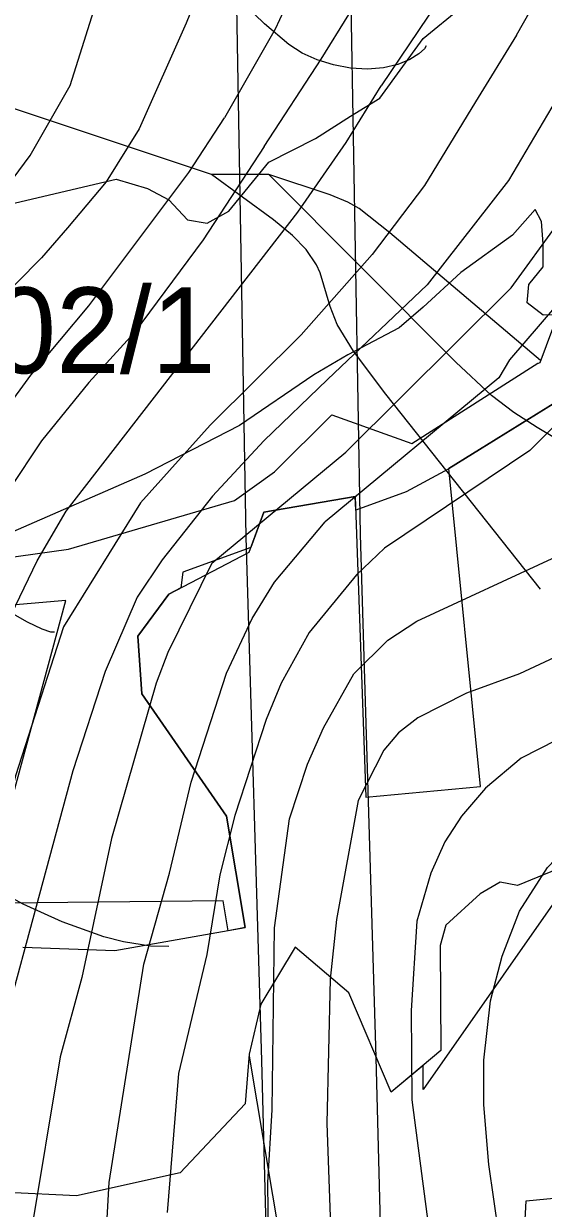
# Model space of a CAD drawing. Extents: x -709584 to -702006, y -1161789 to -1157496.
# Drawn here: x -706934.9 to -706844, y -1160147.8 to -1159940.6 of the extents above; entities that cross this region are included whole.
import ezdxf

# ---------------------------------------------------------------- set-up
doc = ezdxf.new("R2010")
doc.units = 0
for name, color, linetype in [('120_vrstevnice hlavní', 7, 'Continuous'), ('122_vrstevnice základní', 7, 'Continuous'), ('408_BPEJ_linie', 7, 'Continuous'), ('411_akumulovaný odtok', 7, 'Continuous'), ('419_LPIS PB', 7, 'Continuous'), ('419_LPIS PB_kod', 7, 'Continuous'), ('735_OP sítí TI', 7, 'Continuous')]:
    doc.layers.add(name, color=color, linetype=linetype)

msp = doc.modelspace()

# ---------------------------------------------------------------- linework, layer by layer
at = {"layer": '120_vrstevnice hlavní'}
for points in [[(-706753.27, -1159765.73), (-706777.93, -1159786.73), (-706799.82, -1159805.13), (-706817.65, -1159820.01), (-706848.89, -1159847.78), (-706867.26, -1159866.15), (-706879.41, -1159881.48), (-706886.35, -1159893.34), (-706891.85, -1159904.62), (-706906.45, -1159940.48), (-706914.64, -1159958.98), (-706920.42, -1159968.23), (-706927.19, -1159976.29)], [(-706720.57, -1159816.24), (-706754.24, -1159840.65), (-706777.42, -1159857.69), (-706786.98, -1159865.84), (-706797.79, -1159877.42), (-706806.52, -1159889.82), (-706814.32, -1159902.85), (-706826.3, -1159926.72), (-706838.7, -1159948.78), (-706850.08, -1159968), (-706864.28, -1159986.25), (-706881.73, -1160002.84), (-706892.86, -1160013.54), (-706901.83, -1160023.23), (-706910.65, -1160034.37), (-706914.99, -1160040.88), (-706920.63, -1160053.9), (-706926.28, -1160071.26), (-706944.21, -1160137.5), (-706945.95, -1160149.65)], [(-706774.69, -1159924.87), (-706799.13, -1159970.58), (-706804.34, -1159985.34), (-706807.38, -1160006.17), (-706811.86, -1160021.79), (-706817.5, -1160032.2), (-706820.69, -1160036.97), (-706828.79, -1160044.5), (-706835.15, -1160048.26), (-706848.17, -1160054.33), (-706857.43, -1160057.66), (-706865.96, -1160062), (-706869.29, -1160064.6), (-706871.89, -1160067.64), (-706876.37, -1160076.46), (-706880.13, -1160097.29), (-706881.29, -1160107.71), (-706881.87, -1160132.87), (-706881.15, -1160152.54)], [(-706927.19, -1159976.29), (-706931.75, -1159981.56), (-706940.36, -1159990.26), (-706948.49, -1160000.97), (-706955.35, -1160012.53), (-706962.29, -1160026.42), (-706969.52, -1160044.06), (-706977.48, -1160067.21), (-706982.11, -1160084.56), (-706989.4, -1160119.38), (-706995.5, -1160142.99), (-707002.82, -1160167.85), (-707007.82, -1160187.71)]]:
    msp.add_lwpolyline(points, dxfattribs=at)
at = {"layer": '122_vrstevnice základní'}
for points in [[(-706892.81, -1159962.06), (-706882.86, -1159946.78), (-706873.18, -1159931.12), (-706865.1, -1159915.53), (-706860.46, -1159904.12), (-706855.16, -1159893.55), (-706849.04, -1159883.65), (-706840.93, -1159873.62), (-706830.14, -1159862.79), (-706811.17, -1159847.63), (-706780.23, -1159821.28), (-706758.68, -1159803.4), (-706742.7, -1159790.44), (-706728.56, -1159778.47), (-706712.33, -1159760.5), (-706701.57, -1159744.25), (-706688.46, -1159725.96), (-706675.77, -1159704.54), (-706662.08, -1159682.75), (-706646.22, -1159659.65)], [(-706650.66, -1159692.43), (-706660.45, -1159706.17), (-706665.61, -1159714.65), (-706676.19, -1159731.72), (-706691.34, -1159755.31), (-706705.07, -1159773.41), (-706716.39, -1159786.43), (-706730.17, -1159799.55), (-706770.72, -1159830.91), (-706789.82, -1159844.1), (-706814.32, -1159865.65), (-706827.19, -1159878.59), (-706833.7, -1159887.12), (-706843.68, -1159904.48), (-706859.29, -1159932.03), (-706872.34, -1159951.47)], [(-706721.94, -1159748.41), (-706730.59, -1159760.82), (-706742.26, -1159771.6), (-706754.76, -1159782.56), (-706811.57, -1159828.03), (-706847.73, -1159861.09), (-706860.96, -1159878.05), (-706870.48, -1159893.22), (-706876.33, -1159907.78), (-706883.32, -1159925.2), (-706890.86, -1159941.57), (-706899.72, -1159957.09)], [(-706901.94, -1160034.93), (-706878.5, -1160015.52), (-706849.61, -1159986.78), (-706841.37, -1159975.5), (-706821.12, -1159939.85), (-706807.38, -1159911.34), (-706797.19, -1159894.26), (-706784.64, -1159877.2), (-706766.31, -1159858.07), (-706742.37, -1159838.77), (-706703.06, -1159810.72), (-706686.98, -1159797.26), (-706669.15, -1159780.66)], [(-706662, -1159786.17), (-706683.4, -1159804.81), (-706723.19, -1159832.42), (-706744.52, -1159849.25), (-706769.77, -1159871.5), (-706778.88, -1159882.2), (-706787.27, -1159893.92), (-706795.37, -1159907.52), (-706806.65, -1159930.95), (-706831.53, -1159975.5), (-706839.2, -1159986.93), (-706849.9, -1159999.37), (-706851.78, -1160002.55), (-706882.16, -1160027.72)], [(-706848.67, -1159942.59), (-706839.9, -1159927.05), (-706831.63, -1159911.52), (-706822.83, -1159894.4), (-706816.99, -1159883.99), (-706811.86, -1159878.15), (-706799.71, -1159864.99), (-706780.04, -1159848.94), (-706776.28, -1159846.62), (-706725.76, -1159810.42)], [(-706940.69, -1159973.06), (-706933.74, -1159963.66), (-706926.75, -1159951.43), (-706921.2, -1159933.78), (-706914.65, -1159916.88), (-706907.63, -1159902.82), (-706896.46, -1159880.86), (-706882.04, -1159862.88)], [(-706850.92, -1160158.33), (-706853.52, -1160140.11), (-706854.39, -1160129.69), (-706854.39, -1160121.88), (-706853.23, -1160111.47), (-706851.21, -1160103.66), (-706848.17, -1160095.84), (-706843.25, -1160088.18), (-706836.31, -1160080.95), (-706829.36, -1160076.17), (-706812.3, -1160070.39), (-706793.78, -1160063.59), (-706788.43, -1160059.97), (-706781.63, -1160052.45), (-706778.3, -1160044.93), (-706777.29, -1160039.14), (-706777.87, -1160027.57), (-706781.63, -1160010.22), (-706782.35, -1160004.43), (-706782.35, -1159998.64), (-706780.47, -1159989.97), (-706775.99, -1159978.39), (-706759.21, -1159945.41), (-706750.24, -1159924.58)], [(-706769.48, -1159937.31), (-706773.68, -1159945.12), (-706784.09, -1159970.87), (-706788.57, -1159986.49), (-706791.03, -1159999.51), (-706791.61, -1160025.55), (-706793.06, -1160030.75), (-706798.55, -1160039.72), (-706806.51, -1160047.24), (-706817.79, -1160055.34), (-706827.05, -1160060.26), (-706838.62, -1160064.31), (-706847.88, -1160069.08), (-706854.1, -1160074.29), (-706858.29, -1160079.21), (-706861.19, -1160083.69), (-706863.64, -1160089.19), (-706866.1, -1160097.58), (-706867.12, -1160113.2), (-706866.97, -1160128.82), (-706862.2, -1160165.27)], [(-706848.67, -1159942.59), (-706855.83, -1159954.29), (-706864.75, -1159968.89), (-706873.9, -1159980.95), (-706886.33, -1159995.04), (-706902.24, -1160010.83), (-706914.42, -1160024.39), (-706927.87, -1160046.09), (-706936.26, -1160072.12), (-706941.46, -1160093.82), (-706948.84, -1160119.86), (-706952.89, -1160137.21), (-706956.22, -1160158.62)], [(-706966.92, -1160156.31), (-706960.99, -1160127.67), (-706950.72, -1160088.61), (-706948.26, -1160075.59), (-706943.92, -1160059.97), (-706940.88, -1160051.87), (-706932.5, -1160034.52), (-706927.43, -1160025.84), (-706886.93, -1159973.54), (-706878.46, -1159961.35), (-706872.34, -1159951.47)], [(-706988.33, -1160162.09), (-706976.9, -1160112.62), (-706976.03, -1160104.81), (-706972.71, -1160089.19), (-706966.78, -1160068.36), (-706961.14, -1160052.45), (-706949.13, -1160026.42), (-706941.92, -1160013.46), (-706933.62, -1160002.09), (-706923.47, -1159989.92), (-706906, -1159966.65), (-706899.72, -1159957.09)], [(-706892.81, -1159962.06), (-706903.5, -1159978.38), (-706915.53, -1159994.68), (-706923.46, -1160003.38), (-706931.74, -1160013.58), (-706937.41, -1160022.08), (-706948.12, -1160047.53), (-706960.84, -1160084.27), (-706969.52, -1160125.93), (-706971.69, -1160136.34), (-706977.48, -1160176.27)], [(-706892, -1160158.33), (-706892.14, -1160143.29), (-706891.42, -1160130.56), (-706890.98, -1160098.74), (-706888.38, -1160079.64), (-706885.2, -1160070.1), (-706882.45, -1160063.73), (-706877.1, -1160054.33), (-706871.17, -1160048.4), (-706866.1, -1160045.07), (-706841.66, -1160033.79), (-706833.41, -1160026.99), (-706825.46, -1160016.58), (-706823.58, -1160012.53), (-706820.69, -1160002.98), (-706819.82, -1159995.61)], [(-706836.28, -1160005.21), (-706846.36, -1160015.24), (-706871.75, -1160032.34), (-706876.66, -1160036.97), (-706884.91, -1160047.1), (-706889.83, -1160055.92), (-706892.43, -1160062.29), (-706897.93, -1160079.07), (-706900.53, -1160089.48), (-706902.84, -1160103.37), (-706907.76, -1160124.2), (-706909.79, -1160148.5)], [(-706920.63, -1160155.73), (-706919.91, -1160143.29), (-706913.84, -1160105.1), (-706909.35, -1160089.19), (-706905.59, -1160073.28), (-706899.37, -1160054.19), (-706894.89, -1160044.64), (-706890.98, -1160038.28), (-706882.16, -1160027.72)], [(-706901.94, -1160034.93), (-706909.64, -1160050.57), (-706911.67, -1160055.92), (-706919.48, -1160083.12), (-706924.69, -1160107.42), (-706928.45, -1160121.3), (-706933.65, -1160152.54)]]:
    msp.add_lwpolyline(points, dxfattribs=at)
at = {"layer": '408_BPEJ_linie'}
for points in [[(-706945, -1160035), (-706927, -1160032.5), (-706898, -1160024), (-706891, -1160019), (-706881, -1160009), (-706867, -1160014), (-706844.94, -1160000), (-706844.86, -1159999.95), (-706844.53, -1159999.85), (-706839, -1159985), (-706829, -1159980), (-706806, -1159963.5), (-706799.5, -1159954.5), (-706805.5, -1159944.5), (-706813, -1159945), (-706840.5, -1159918.5)], [(-706830.8, -1160000), (-706860.5, -1160018.4), (-706860.5, -1160018.45), (-706868, -1160022.5), (-706876.8, -1160025.66), (-706876.88, -1160023.3), (-706892.85, -1160026.04), (-706895.12, -1160032.23), (-706907, -1160036.5), (-706907.39, -1160039.29), (-706909.5, -1160040.4), (-706914.9, -1160047.7), (-706914.2, -1160057.8), (-706899.4, -1160079.2), (-706896.1, -1160098.7), (-706899.12, -1160099.23), (-706900, -1160094), (-706943.5, -1160094.5)], [(-706937.5, -1160078.5), (-706927.5, -1160041.5), (-706974, -1160045.5)], [(-706812.49, -1160097.78), (-706813.99, -1160094.27), (-706814.99, -1160088.74), (-706816.49, -1160084.22), (-706817.46, -1160082.87), (-706837, -1160087), (-706865, -1160127), (-706865, -1160122.8), (-706870.6, -1160127.5), (-706878, -1160110.1), (-706887.4, -1160102.1), (-706893.4, -1160112.1), (-706895.4, -1160120.8), (-706895.43, -1160121.18), (-706890, -1160153.5)], [(-706848, -1160165), (-706847, -1160146.5), (-706821, -1160144), (-706812, -1160142), (-706791.5, -1160133.5), (-706757.99, -1160125.12), (-706754.42, -1160122.89), (-706753.87, -1160121.78), (-706754.5, -1160118), (-706770.5, -1160117), (-706779.79, -1160103.58), (-706784.96, -1160101.8), (-706790.12, -1160100.86), (-706799.5, -1160106), (-706801.22, -1160102.34), (-706804.48, -1160102.8), (-706807.98, -1160102.8), (-706809.98, -1160100.79), (-706812.49, -1160097.78)]]:
    msp.add_lwpolyline(points, dxfattribs=at)
at = {"layer": '411_akumulovaný odtok'}
for p, q in [((-706901.99, -1159967), (-706976.99, -1159942)), ((-706891.99, -1159967), (-706901.99, -1159967))]:
    msp.add_line(p, q, dxfattribs=at)
for points in [[(-706864.49, -1159944.5), (-706864.78, -1159945), (-706865.76, -1159945.85), (-706867.33, -1159946.84), (-706869.42, -1159947.74), (-706871.92, -1159948.33), (-706874.72, -1159948.53), (-706877.69, -1159948.35), (-706880.69, -1159947.81), (-706883.56, -1159946.93), (-706886.16, -1159945.75), (-706888.52, -1159944.21), (-706892.77, -1159940.65), (-706904.9, -1159928.81), (-706911.09, -1159923.26), (-706913.25, -1159921.64), (-706915.48, -1159920.21), (-706917.83, -1159919.05), (-706920.17, -1159918.26), (-706922.61, -1159917.71), (-706927.68, -1159917.08), (-706932.91, -1159916.83), (-706946.17, -1159916.55)], [(-706844.49, -1160039.5), (-706871.52, -1160005.38), (-706877.16, -1159997.87), (-706880.02, -1159993.19), (-706881.28, -1159990.08), (-706883.03, -1159984.17), (-706883.63, -1159982.79), (-706885.45, -1159980.12), (-706887.84, -1159977.67), (-706891.15, -1159974.93), (-706901.99, -1159967)], [(-706844.49, -1159999.5), (-706870.81, -1159977.16), (-706876.22, -1159972.95), (-706878.16, -1159971.84), (-706881.26, -1159970.52), (-706891.99, -1159967)], [(-706826.99, -1160022), (-706845.09, -1160011.23), (-706849.15, -1160008.6), (-706853.06, -1160005.62), (-706859.29, -1159999.77), (-706891.99, -1159967)], [(-706929.49, -1160047), (-706930.1, -1160047.02), (-706931.62, -1160046.5), (-706934.21, -1160045.26), (-706945.75, -1160038.74)], [(-706909.49, -1160102), (-706912.71, -1160101.95), (-706917.43, -1160101.19), (-706920.84, -1160100.3), (-706928.12, -1160097.7), (-706934.96, -1160094.58), (-706956.38, -1160082.81), (-706964.45, -1160078.67), (-706972.49, -1160075.23), (-706983.32, -1160071.46), (-706991.55, -1160069.1), (-706997.12, -1160067.93), (-707002.57, -1160067.28), (-707019.07, -1160066.21), (-707024.68, -1160065.36), (-707027.93, -1160064.61), (-707035.08, -1160062.6), (-707051.99, -1160057)]]:
    msp.add_lwpolyline(points, dxfattribs=at)
at = {"layer": '419_LPIS PB'}
for points in [[(-706815.5, -1159930.8), (-706816.4, -1159941.3), (-706815.8, -1159963.7), (-706826.3, -1159981.3), (-706831.6, -1159984), (-706834.5, -1159988.1), (-706839, -1159991.5), (-706844, -1159991.6), (-706846.8, -1159989.4), (-706846.5, -1159986.2), (-706844, -1159983.1), (-706844, -1159979.1), (-706844.3, -1159975.2), (-706845.4, -1159973.1), (-706849.4, -1159977.6), (-706858.4, -1159984.1), (-706865, -1159990.2), (-706869.2, -1159993.8), (-706878.2, -1159998.5), (-706884.1, -1160002), (-706897.1, -1160010.9), (-706913.7, -1160019.4), (-706945.1, -1160033.1)], [(-706944.3, -1159973.8), (-706918.7, -1159967.8), (-706913.2, -1159969.4), (-706909.5, -1159971.4), (-706906.2, -1159974.9), (-706902.8, -1159975.5), (-706899, -1159973.4), (-706892, -1159964.8), (-706883.8, -1159960.7), (-706877.7, -1159956.77), (-706872.6, -1159953.6), (-706865, -1159943.2), (-706858.3, -1159937.7)], [(-706935, -1160102.1), (-706918.9, -1160102.7), (-706896.1, -1160098.7), (-706899.4, -1160079.2), (-706914.2, -1160057.8), (-706914.9, -1160047.7), (-706909.5, -1160040.4), (-706895.4, -1160033), (-706892.85, -1160026.04), (-706876.88, -1160023.3), (-706875, -1160075.9), (-706855, -1160074), (-706860.5, -1160018.4), (-706808.2, -1159986)], [(-706840.4, -1160088), (-706848.5, -1160091.3), (-706851.53, -1160090.75), (-706855.03, -1160092.76), (-706861.04, -1160098.28), (-706862.04, -1160101.8), (-706861.9, -1160120.2), (-706870.6, -1160127.5), (-706878, -1160110.1), (-706887.4, -1160102.1), (-706893.4, -1160112.1), (-706895.4, -1160120.8), (-706896.1, -1160129.5), (-706907.5, -1160141.6), (-706925.6, -1160145.6), (-706937.7, -1160145)]]:
    msp.add_lwpolyline(points, dxfattribs=at)
at = {"layer": '735_OP sítí TI'}
for points in [[(-706890.9, -1160211.71), (-706893.24, -1160121.95), (-706895.97, -1160030.39), (-706898.81, -1159867.84), (-706900.66, -1159770.33), (-706903.19, -1159670.86), (-706905.78, -1159542.43), (-706907.99, -1159419.91), (-706892.79, -1159373.15), (-706876.98, -1159324.93), (-706804.64, -1159203.21), (-706740.99, -1159097), (-706691.31, -1159013.46)], [(-706870.8, -1160215.44), (-706873.24, -1160121.39), (-706875.97, -1160029.91), (-706878.81, -1159867.48), (-706880.66, -1159769.89), (-706883.19, -1159670.4), (-706885.78, -1159542.05), (-706887.93, -1159422.91), (-706873.77, -1159379.35), (-706858.66, -1159333.25), (-706787.46, -1159213.45), (-706723.81, -1159107.26), (-706674.12, -1159023.69)]]:
    msp.add_lwpolyline(points, dxfattribs=at)

# ---------------------------------------------------------------- texts
at = {"layer": '419_LPIS PB_kod'}
msp.add_text('6902/1', height=15, dxfattribs=at).set_placement((-706962.66, -1160001.72))

doc.saveas('drawing.dxf')
